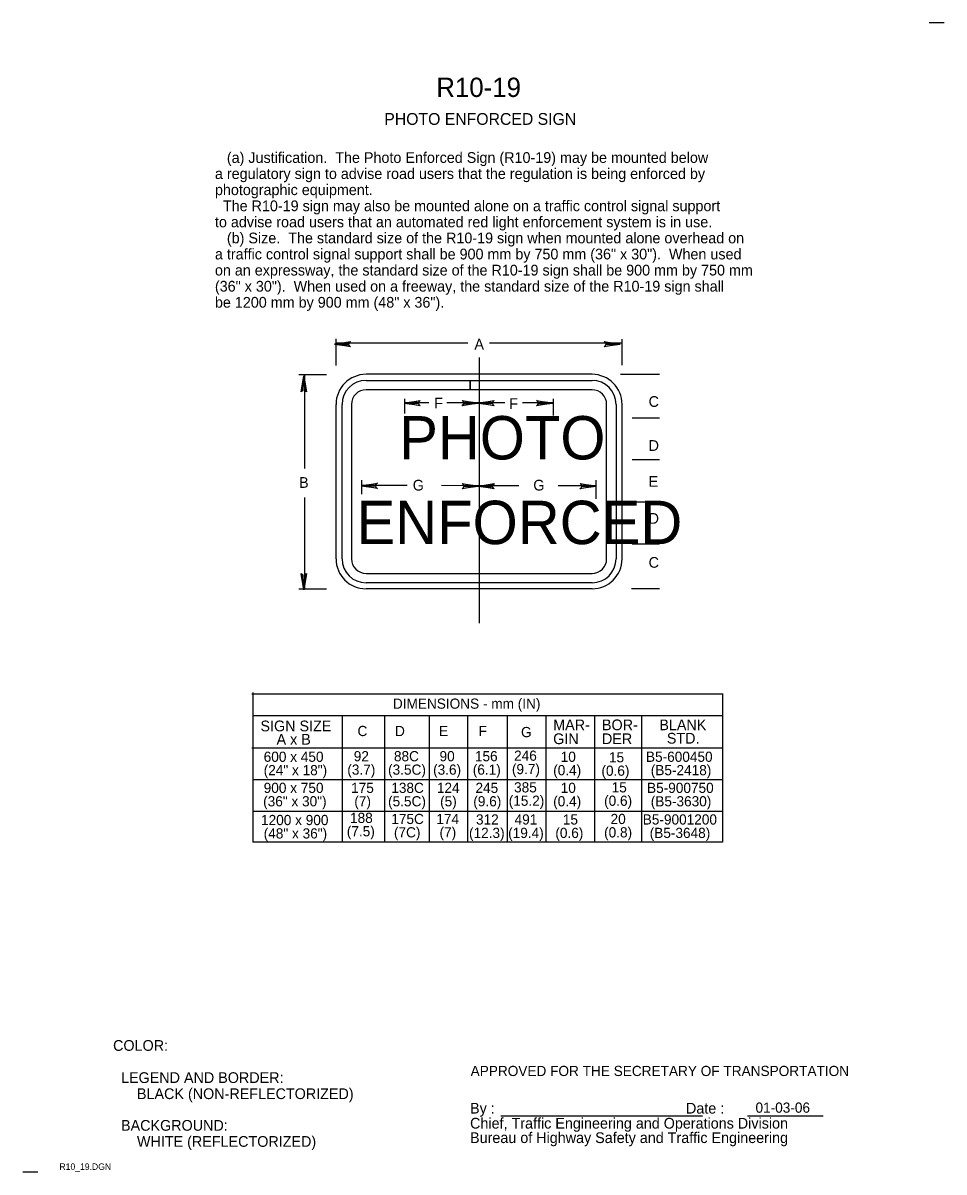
# Model space of a CAD drawing. Extents: x 0.004 to 0.219, y 0.004 to 0.272.
import ezdxf

# ---------------------------------------------------------------- set-up
doc = ezdxf.new("R2010")
doc.units = 0
for name, color, linetype in [('1', 7, 'Continuous'), ('2', 7, 'Continuous'), ('3', 7, 'Continuous'), ('4', 7, 'Continuous'), ('63', 7, 'Continuous')]:
    doc.layers.add(name, color=color, linetype=linetype)

# ---------------------------------------------------------------- blocks, each defined once
blk = doc.blocks.new('RARROW')
at = {"layer": '3'}
for p, q in [((-2.156, 0.285), (-2.2665, 0.384625)), ((-2.2665, 0.384625), (0, 0)), ((0, 0), (-2.2665, -0.379125)), ((-2.156, 0.285), (-2.075625, 0.12075)), ((0, 0), (-2.156, 0.285)), ((-2.14975, -0.2705), (0, 0)), ((-2.075625, 0.12075), (0, 0)), ((0, 0), (-2.074, -0.108)), ((-2.2665, -0.379125), (-2.14975, -0.2705)), ((-2.074, -0.108), (-2.14975, -0.2705))]:
    blk.add_line(p, q, dxfattribs=at)

msp = doc.modelspace()

# ---------------------------------------------------------------- linework, layer by layer
at = {"layer": '1'}
for p, q in [((0.11046, 0.1938), (0.11046, 0.13182)), ((0.06841, 0.18983), (0.07491, 0.18983)), ((0.06987, 0.16791), (0.06987, 0.18983)), ((0.13681, 0.18984), (0.08411, 0.18984)), ((0.08411, 0.18844), (0.10838, 0.18844)), ((0.10838, 0.18844), (0.10838, 0.18624)), ((0.10838, 0.18844), (0.10838, 0.18624)), ((0.10838, 0.18624), (0.10838, 0.18844)), ((0.10838, 0.18844), (0.13681, 0.18844)), ((0.15252, 0.18983), (0.14602, 0.18983)), ((0.10838, 0.18624), (0.08411, 0.18624)), ((0.13681, 0.18624), (0.10838, 0.18624)), ((0.07711, 0.14684), (0.07711, 0.18284)), ((0.07851, 0.14684), (0.07851, 0.18284)), ((0.08071, 0.18284), (0.08071, 0.14684)), ((0.09311, 0.18414), (0.09311, 0.18072)), ((0.12776, 0.18414), (0.12776, 0.18026)), ((0.14021, 0.14684), (0.14021, 0.18284)), ((0.14241, 0.18284), (0.14241, 0.14684)), ((0.14381, 0.14684), (0.14381, 0.18284)), ((0.14381, 0.14684), (0.14381, 0.18284)), ((0.15252, 0.17965), (0.14613, 0.17965)), ((0.15252, 0.16987), (0.14613, 0.16987)), ((0.08313, 0.16194), (0.08313, 0.16516)), ((0.13779, 0.16079), (0.13779, 0.16516)), ((0.06987, 0.13984), (0.06987, 0.16114)), ((0.14613, 0.16009), (0.15252, 0.16009)), ((0.14613, 0.15031), (0.15252, 0.15031)), ((0.08411, 0.14344), (0.13681, 0.14344)), ((0.06841, 0.13984), (0.07491, 0.13984)), ((0.13681, 0.14124), (0.08411, 0.14124)), ((0.13681, 0.13984), (0.08411, 0.13984)), ((0.15252, 0.13984), (0.14602, 0.13984)), ((0.11556, 0.01695), (0.16257, 0.01695)), ((0.17308, 0.01695), (0.19069, 0.01695))]:
    msp.add_line(p, q, dxfattribs=at)
for centre, radius, start, end in [((0.08411, 0.18284), 0.007, 90, 180), ((0.08411, 0.18284), 0.0056, 90, 180), ((0.13681, 0.18284), 0.007, 0, 90), ((0.13681, 0.18284), 0.0056, 0, 90), ((0.08411, 0.18284), 0.0034, 90, 180), ((0.13681, 0.18284), 0.0034, 0, 90), ((0.08411, 0.14684), 0.007, 180, 270), ((0.08411, 0.14684), 0.0056, 180, 270), ((0.08411, 0.14684), 0.0034, 180, 270), ((0.13681, 0.14684), 0.007, 270, 0), ((0.13681, 0.14684), 0.0034, 270, 0), ((0.13681, 0.14684), 0.0056, 270, 0)]:
    msp.add_arc(centre, radius, start, end, dxfattribs=at)
at = {"layer": '3'}
for p, q in [((0.07711, 0.19187), (0.07711, 0.19815)), ((0.10784, 0.19714), (0.07711, 0.19714)), ((0.1438, 0.19714), (0.11291, 0.19714)), ((0.14381, 0.19197), (0.1438, 0.198)), ((0.14346, 0.18985), (0.14923, 0.18985)), ((0.09877, 0.18321), (0.09311, 0.18321)), ((0.11046, 0.18321), (0.10293, 0.18321)), ((0.11644, 0.18321), (0.11046, 0.18321)), ((0.12776, 0.18321), (0.1206, 0.18321)), ((0.09374, 0.1639), (0.08313, 0.16391)), ((0.11046, 0.16388), (0.10174, 0.16389)), ((0.1197, 0.16387), (0.11046, 0.16388)), ((0.13779, 0.16387), (0.12891, 0.16388)), ((0.0575, 0.11538), (0.16725, 0.11538)), ((0.05774, 0.11563), (0.05774, 0.08079)), ((0.16726, 0.11544), (0.16726, 0.08079)), ((0.16726, 0.11025), (0.05774, 0.11025)), ((0.07858, 0.11025), (0.07858, 0.08079)), ((0.1374, 0.11025), (0.1374, 0.08079)), ((0.14834, 0.11025), (0.14834, 0.08079)), ((0.0575, 0.10275), (0.16725, 0.10275)), ((0.05775, 0.09538), (0.16725, 0.09538)), ((0.05775, 0.088), (0.16725, 0.088)), ((0.16726, 0.08079), (0.05774, 0.08079))]:
    msp.add_line(p, q, dxfattribs=at)
for points in [[(0.08839, 0.11025), (0.08839, 0.08079)], [(0.09882, 0.11025), (0.09882, 0.08079)], [(0.10774, 0.11025), (0.10774, 0.08079)], [(0.11699, 0.11025), (0.11699, 0.08079)], [(0.12602, 0.11025), (0.12602, 0.08079)]]:
    msp.add_lwpolyline(points, dxfattribs=at)
at = {"layer": '63'}
for p, q in [((0.21888, 0.27175), (0.21538, 0.27175)), ((0.00762, 0.00387), (0.00413, 0.00387))]:
    msp.add_line(p, q, dxfattribs=at)

# ---------------------------------------------------------------- block references
at = {"layer": '3'}
for p, xscale, yscale, rotation in [((0.07675, 0.19687), 0.0016545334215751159, 0.0016366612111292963, 179.91708286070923), ((0.14338, 0.19687), 0.0016545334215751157, 0.001636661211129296, -0.08291713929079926), ((0.06963, 0.1895), 0.0016545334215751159, 0.0016366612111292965, 90.08291713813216), ((0.093, 0.18313), 0.0016545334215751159, 0.0016366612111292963, 179.91708286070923), ((0.11025, 0.18313), 0.0016545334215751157, 0.001636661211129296, -0.08291713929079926), ((0.11025, 0.18313), 0.0016545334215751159, 0.0016366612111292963, 179.91708286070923), ((0.12763, 0.18313), 0.0016545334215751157, 0.001636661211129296, -0.08291713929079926), ((0.083, 0.16387), 0.0016545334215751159, 0.0016366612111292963, 179.91708286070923), ((0.11025, 0.16375), 0.0016545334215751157, 0.001636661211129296, -0.08291713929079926), ((0.11025, 0.16375), 0.0016545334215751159, 0.0016366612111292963, 179.91708286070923), ((0.13775, 0.16375), 0.0016545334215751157, 0.001636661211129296, -0.08291713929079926), ((0.06963, 0.13962), 0.0016545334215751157, 0.0016366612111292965, -89.91708286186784)]:
    msp.add_blockref('RARROW', p, dxfattribs=dict(at, xscale=xscale, yscale=yscale, rotation=rotation))

# ---------------------------------------------------------------- texts
at = {"layer": '1'}
for s, height, p in [('R10-19', 0.0045, (0.1005, 0.2545)), ('PHOTO ENFORCED SIGN', 0.0027503, (0.08837, 0.248)), ('PHOTO', 0.010107, (0.09187, 0.17)), ('ENFORCED', 0.010125, (0.08188, 0.15025)), ('175', 0.002375, (0.08063, 0.09225)), ('138C', 0.002375, (0.09, 0.09225)), ('124', 0.002375, (0.10063, 0.09225)), ('245', 0.002375, (0.10963, 0.09225)), ('385', 0.002375, (0.11863, 0.09237)), ('10', 0.002375, (0.1295, 0.09225)), ('(7)', 0.002375, (0.08138, 0.08912)), ('(5.5C)', 0.002375, (0.08925, 0.08912)), ('(5)', 0.002375, (0.10138, 0.08912)), ('(9.6)', 0.002375, (0.10912, 0.08912)), ('(15.2)', 0.002375, (0.11738, 0.08925)), ('(0.4)', 0.002375, (0.12775, 0.08912)), ('20', 0.002375, (0.14113, 0.085)), ('B5-9001200', 0.002375, (0.14863, 0.08488)), ('(0.8)', 0.002375, (0.13962, 0.08188)), ('(B5-3648)', 0.002375, (0.15025, 0.08175)), ('COLOR:', 0.0025, (0.02513, 0.03213)), ('  LEGEND AND BORDER:', 0.0024998, (0.02513, 0.02463)), ('APPROVED FOR THE SECRETARY OF TRANSPORTATION', 0.0023752, (0.1085, 0.02625)), ('      BLACK (NON-REFLECTORIZED)', 0.0024998, (0.02513, 0.02088)), ('By :                                                Date :', 0.0024998, (0.10837, 0.0175)), ('Chief, Traffic Engineering and Operations Division', 0.0024998, (0.10837, 0.014)), ('  BACKGROUND:', 0.0024998, (0.02513, 0.0135)), ('      WHITE (REFLECTORIZED)', 0.0024998, (0.02513, 0.00975)), ('Bureau of Highway Safety and Traffic Engineering', 0.0024998, (0.10837, 0.01063)), ('R10_19.DGN', 0.0015, (0.01263, 0.00438))]:
    msp.add_text(s, height=height, dxfattribs=at).set_placement(p)
at = {"layer": '2'}
for s, p in [('   (a) Justification.  The Photo Enforced Sign (R10-19) may be mounted below', (0.04888, 0.23913)), ('a regulatory sign to advise road users that the regulation is being enforced by', (0.04888, 0.23538)), ('photographic equipment.', (0.04888, 0.23162)), ('  The R10-19 sign may also be mounted alone on a traffic control signal support', (0.04888, 0.22787)), ('to advise road users that an automated red light enforcement system is in use.', (0.04888, 0.22412)), ('   (b) Size.  The standard size of the R10-19 sign when mounted alone overhead on', (0.04888, 0.22038)), ('a traffic control signal support shall be 900 mm by 750 mm (36" x 30").  When used', (0.04888, 0.21663)), ('on an expressway, the standard size of the R10-19 sign shall be 900 mm by 750 mm', (0.04888, 0.21288)), ('(36" x 30").  When used on a freeway, the standard size of the R10-19 sign shall', (0.04888, 0.20913)), ('be 1200 mm by 900 mm (48" x 36").', (0.04888, 0.20538))]:
    msp.add_text(s, height=0.0024998, dxfattribs=at).set_placement(p)
at = {"layer": '3'}
for s, rotation, p in [('A', 359.9171, (0.10938, 0.19562)), ('F', 359.9171, (0.1, 0.18188)), ('F', 0.0829, (0.1175, 0.18175)), ('C', 0.0829, (0.15, 0.18225)), ('D', 359.9171, (0.15, 0.172)), ('E', 0.0829, (0.15, 0.16362)), ('B', 0.0829, (0.0685, 0.16337)), ('G', 359.9171, (0.095, 0.16275)), ('G', 0.0829, (0.12312, 0.16275)), ('D', 0.0829, (0.15, 0.155)), ('C', 359.9171, (0.15, 0.14475))]:
    msp.add_text(s, height=0.0025, rotation=rotation, dxfattribs=at).set_placement(p)
for s, height, p in [('DIMENSIONS - mm (IN)', 0.0023752, (0.09037, 0.11188)), ('SIGN SIZE', 0.0025, (0.0595, 0.10662)), ('C', 0.00238, (0.08213, 0.1055)), ('D', 0.00238, (0.09087, 0.1055)), ('E', 0.00238, (0.10113, 0.1055)), ('F', 0.00238, (0.11038, 0.1055)), ('G', 0.00238, (0.12025, 0.10525)), ('MAR-', 0.0025, (0.12775, 0.10687)), ('BOR-', 0.0025, (0.13912, 0.10687)), ('BLANK', 0.0025, (0.1525, 0.10687)), ('A x B', 0.0025, (0.06325, 0.1035)), ('GIN', 0.0025, (0.12775, 0.10363)), ('DER', 0.0025, (0.13912, 0.10363)), ('STD.', 0.0025, (0.15425, 0.10375)), ('600 x 450', 0.002375, (0.06025, 0.0995)), ('92', 0.002375, (0.08125, 0.09963)), ('88C', 0.002375, (0.09062, 0.09963)), ('90', 0.002375, (0.10125, 0.09963)), ('156', 0.002375, (0.1095, 0.09963)), ('246', 0.002375, (0.11863, 0.09975)), ('10', 0.002375, (0.1295, 0.0995)), ('B5-600450', 0.002375, (0.14938, 0.0995)), ('(9.7)', 0.002375, (0.11813, 0.09663)), ('15', 0.002375, (0.14075, 0.09938)), ('(24" x 18")', 0.0023752, (0.06025, 0.09638)), ('(3.7)', 0.002375, (0.07975, 0.0965)), ('(3.5C)', 0.002375, (0.08925, 0.0965)), ('(3.6)', 0.002375, (0.09975, 0.0965)), ('(6.1)', 0.002375, (0.109, 0.0965)), ('(0.4)', 0.002375, (0.12775, 0.09638)), ('(0.6)', 0.002375, (0.139, 0.09625)), ('(B5-2418)', 0.002375, (0.1505, 0.09638)), ('900 x 750', 0.002375, (0.06025, 0.09225)), ('15', 0.002375, (0.14138, 0.09237)), ('B5-900750', 0.002375, (0.14963, 0.09225)), ('(36" x 30")', 0.0023752, (0.06012, 0.08912)), ('(0.6)', 0.002375, (0.13962, 0.08925)), ('(B5-3630)', 0.002375, (0.1505, 0.08912)), ('1200 x 900', 0.002375, (0.05963, 0.08475)), ('188', 0.002375, (0.08038, 0.08525)), ('175C', 0.002375, (0.09, 0.085)), ('174', 0.002375, (0.1005, 0.085)), ('312', 0.002375, (0.10975, 0.08488)), ('491', 0.002375, (0.11875, 0.08488)), ('15', 0.002375, (0.13, 0.08488)), ('(48" x 36")', 0.0023752, (0.06025, 0.08163)), ('(7.5)', 0.002375, (0.07963, 0.08213)), ('(7C)', 0.002375, (0.09062, 0.08188)), ('(7)', 0.002375, (0.10125, 0.08188)), ('(12.3)', 0.002375, (0.10812, 0.08175)), ('(19.4)', 0.002375, (0.11725, 0.08175)), ('(0.6)', 0.002375, (0.12825, 0.08175))]:
    msp.add_text(s, height=height, dxfattribs=at).set_placement(p)
at = {"layer": '4'}
msp.add_text('01-03-06', height=0.002375, dxfattribs=at).set_placement((0.17492, 0.0177))

doc.saveas('drawing.dxf')
